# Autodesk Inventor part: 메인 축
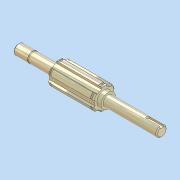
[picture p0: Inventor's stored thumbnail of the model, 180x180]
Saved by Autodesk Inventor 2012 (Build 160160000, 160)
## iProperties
Company: 한국ATC센터
Created: 2014-07
Part Number: 메인 축
Document SubType Name: 모델링
Designer: KYOUNG IL JANG
Mass: 21.4462 g
Surface Area: 72.5109 cm^2
Volume: 21.4462 cm^3
Density: 1 g/cm^3
Material: 기본값
변환 표준: STEP AP214IS
파일 이름: C:\Users\SeoGD\Desktop\?쒗뿕\硫붿씤 異?.stp
전처리기: Build: 253, Release: 2010 SP1 - Date: Wed 07/29/2009
전송 단위: 밀리미터
불확실성: 0.01
Author: KYOUNG IL JANG
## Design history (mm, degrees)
sketch "스케치1"
  geometry: L1 (-69.5, 0)-(69.5, 0); L2 (69.5, 0)-(69.5, 5); L3 (69.5, 5)-(55.5, 5); L4 (55.5, 5)-(55.5, 4.8); L5 (55.5, 4.8)-(54.35, 4.8); L6 (54.35, 4.8)-(54.35, 5); L7 (54.35, 5)-(30.5, 5); L8 (30.5, 5)-(30.5, 9); L9 (30.5, 9)-(-13.5, 9); L10 (-13.5, 9)-(-13.5, 7); L11 (-13.5, 7)-(-17.5, 7); L12 (-17.5, 7)-(-17.5, 5); L13 (-17.5, 5)-(-69.5, 5); L14 (-69.5, 5)-(-69.5, 0); 2 further points
  constraints: 28 end point, 9 parallel, 4 collinear, 2 perpendicular, 1 coincident, 1 horizontal, 1 midpoint
  dimensions: "d2" = 1.15 distance between parallel lines of L6 L4; "d3" = 10 diameter of L3 L1; "d4" = 9.6 diameter of L5 L1; "d6" = 44 distance between parallel lines of L10 L8; "d7" = 4 distance between parallel lines of L12 L10; "d8" = 14 diameter of L11 L1; "d9" = 18 diameter of L9 L1; "d33" = 52 distance from line of L12.end L14; "d37" = 39 distance between parallel lines of L8 L2; "d38" = 14 distance between parallel lines of L2 L4
revolve "회전1" sketch "스케치1" stored, may be unused: angle "d10" = 90 deg
sketch "스케치2"
  geometry: L1 (2.5, 10.712)-(2.5, 8.646); L2 (-2.5, 10.712)-(-2.5, 8.646); A1 r 9 centre (0, 0) between (2.5, 8.646) and (-2.5, 8.646) reference; A2 r 11 centre (0, 0) between (2.5, 10.712) and (-2.5, 10.712); 1 further point
  constraints: 4 end point, 4 point on circle, 2 parallel, 1 centre point, 1 coincident, 1 vertical
  dimensions: "d11" = 22 diameter of A2; "d12" = 5 distance between parallel lines of L1 L2
extrude "돌출1" join sketch "스케치2" stored distance "d13" = 10; taper "d14" = 0 deg
chamfer "모따기1" distance "d15" = 1; stored, may be unused: second distance "d16" = 2, angle "d17" = 45 deg
node "작업 평면1"
node "작업 평면2"
sketch "스케치3"
  geometry: L1 (2.5, 10.712)-(2.5, 10.198); L2 (-2.5, 10.712)-(-2.5, 10.198); A1 r 11 centre (0, 0) between (2.5, 10.712) and (-2.5, 10.712) reference; A2 r 10.5 centre (0, 0) between (2.5, 10.198) and (-2.5, 10.198); 1 further point
  constraints: 4 end point, 2 point on circle, 1 centre point, 1 coincident, 1 parallel, 1 vertical
  dimensions: "d19" = 21 diameter of A2
extrude "돌출2" cut sketch "스케치3" distance "d20" = 1.35; taper "d21" = 0 deg
node "작업 평면3"
sketch "스케치4"
  geometry: L1 (-26, -5)-(-26, 5) reference; L2 (-26, 1.5)-(-12.5, 1.5); L3 (-12.5, -1.5)-(-26, -1.5); A1 r 1.5 centre (-12.5, 0) between (-12.5, -1.5) and (-12.5, 1.5); 2 further points
  constraints: 4 end point, 2 perpendicular, 2 point on circle, 2 point on line, 2 tangent, 1 centre point, 1 horizontal alignment, 1 midpoint
  dimensions: "d25" = 3 distance between parallel lines of L3 L2; "d26" = 15 dimension on A1 L1
extrude "돌출3" cut sketch "스케치4" distance "d27" = 1.8; taper "d28" = 0 deg
chamfer "모따기2" distance "d29" = 1; stored, may be unused: second distance "d30" = 2, angle "d31" = 45 deg
node "솔리드1"
node "솔리드 본체"
node "곡면 본체"
mirror "대칭1"
pattern_circular "원형 패턴1" dims "d23" = 360 deg
node "솔리드2"
other parameters: "d18" = -1.65
